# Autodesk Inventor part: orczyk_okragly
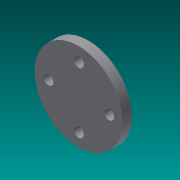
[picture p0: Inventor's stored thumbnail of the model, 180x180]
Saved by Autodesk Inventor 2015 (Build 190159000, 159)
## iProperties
Created: 2016-02
Part Number: orczyk_okragly
Material: Generic
Document SubType Name: Modeling
Designer: Rafał
Density: 1 g/cm^3
Appearance: Default
Author: Rafał
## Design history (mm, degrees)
sketch "Sketch1"
  geometry: C1 r 10.5 at (0, 0); 1 further point
  constraints: 1 centre point, 1 coincident
  dimensions: "d0" = 21 diameter of C1
extrude "Extrusion1" new body sketch "Sketch1" distance "d1" = 2.3; taper "d2" = 0 deg
sketch "Sketch2"
  geometry: C1 r 4.5 at (0, 0); 1 further point
  constraints: 1 centre point, 1 coincident
  dimensions: "d3" = 9 diameter of C1
extrude "Extrusion2" join sketch "Sketch2" distance "d4" = 3.2; taper "d5" = 0 deg
sketch "Sketch3"
  geometry: C1 r 3 at (0, 0); 1 further point
  constraints: 1 centre point, 1 coincident
  dimensions: "d6" = 6 diameter of C1
extrude "Extrusion3" cut sketch "Sketch3" distance "d7" = 3; taper "d8" = 0 deg
sketch "Sketch4"
  geometry: C1 r 1.25 at (0, -7.25); C2 r 1.25 at (0, 7.25); C3 r 1.25 at (-7.25, 0); C4 r 1.25 at (7.25, 0); A1 r 7.25 centre (0, 0) between (0, -7.25) and (0, 7.25); 1 further point
  constraints: 5 centre point, 4 point on circle, 1 coincident
  dimensions: "d9" = 14.5 diameter of A1; "d10" = 2.5 diameter of C1; "d11" = 2.5 diameter of C2; "d12" = 2.5 diameter of C3; "d13" = 2.5 diameter of C4
extrude "Extrusion4" cut sketch "Sketch4" distance "d14" = 3; taper "d15" = 0 deg
body "Solid1"
